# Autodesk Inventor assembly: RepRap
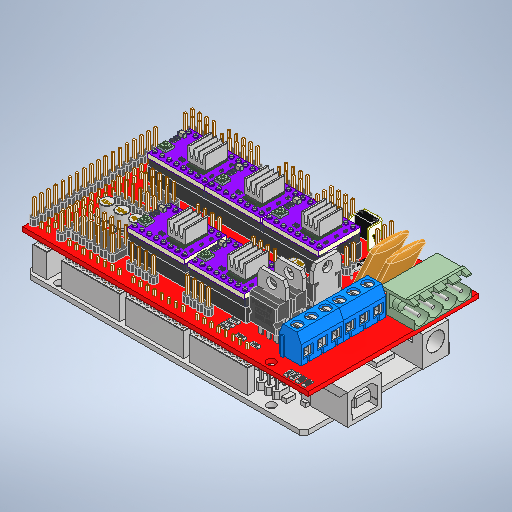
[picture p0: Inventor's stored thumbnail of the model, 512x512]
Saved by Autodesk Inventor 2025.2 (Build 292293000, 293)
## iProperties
Created: 2023-07
Part Number: RepRap
Description: STEP AP214
Document SubType Name: Assembly
Designer: BennF
Title: RepRap.stp
Revision Number: NONE
Preprocessor: Spatial InterOp 3D
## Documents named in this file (3)
- C:\Users\BennF\Nextcloud\Benutzer\CNC JarBeRi\existing parts\Electronics\RepRap A4988 Shied (USE WITHOUT ARDUINO)\reprap-a4988-1.snapshot.1\RepRap\RepRap\RepRap.iam
- C:\Users\BennF\Nextcloud\Benutzer\CNC JarBeRi\existing parts\Electronics\RepRap A4988 Shied (USE WITHOUT ARDUINO)\reprap-a4988-1.snapshot.1\RepRap\RepRap\PART.iam
- C:\Users\BennF\Nextcloud\Benutzer\CNC JarBeRi\existing parts\Electronics\RepRap A4988 Shied (USE WITHOUT ARDUINO)\reprap-a4988-1.snapshot.1\RepRap\RepRap\ARDUINO-MEGA.ipt
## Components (2 placed, 2 different names)
1. PART [sub-assembly]
2. ARDUINO-MEGA
